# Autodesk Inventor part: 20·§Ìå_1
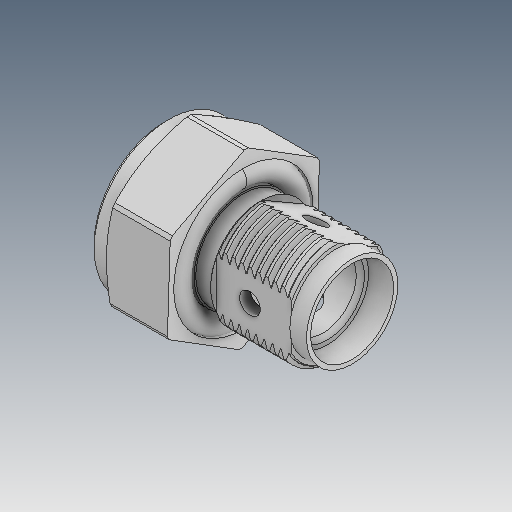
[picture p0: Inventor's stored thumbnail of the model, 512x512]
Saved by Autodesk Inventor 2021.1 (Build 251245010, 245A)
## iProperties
Created: 2019-05
Part Number: 20·§Ìå_1
Material: Ogólny
Document SubType Name: Modeling
Designer: user
Density: 1 g/cm^3
Appearance: Domyślna
Author: user
Revision Number: ÈÎºÎ
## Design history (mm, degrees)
feature "ÊäÈë1"
feature "ÊäÈë2"
node "Bryła1"
node "Bryła2"
